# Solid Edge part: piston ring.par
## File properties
Author: Robert a Rhodes jr
Template: Normal.par
Last saved by: CADCIM
Revision: 16
Application: Solid Edge
Accuracy: 0.99
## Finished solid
Body 1: solid body, 6 faces, 12 edges, 8 vertices.
  Faces by surface: plane 4, cylinder 2
  Edges by curve: line 8, circle 4
Bounding box of the edges (mm): 94.000 x 94.000 x 3.000, from (-47, -47, -3) to (47, 47, 0).
Cylindrical faces by radius (mm): R43 x1, R47 x1
Planar faces by outward normal: +y 1, +z 1, -y 1, -z 1
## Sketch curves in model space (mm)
line (-28.0593, 0, 0) -> (-28.0593, -1, 0)
line (-28.0593, -1, 0) -> (-54.5597, -1, 0)
line (-54.5597, -1, 0) -> (-54.5597, 0, 0)
line (-54.5597, 0, 0) -> (-28.0593, 0, 0)
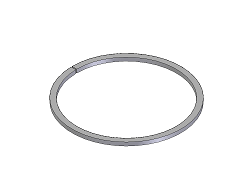
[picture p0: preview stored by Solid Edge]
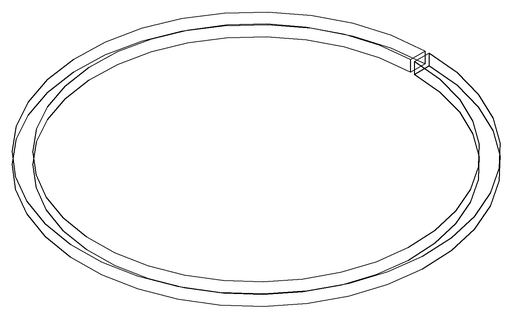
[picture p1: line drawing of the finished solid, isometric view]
